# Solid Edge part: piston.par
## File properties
Author: Robert a Rhodes jr
Template: normal.par
Last saved by: CADCIM
Revision: 11
Application: Solid Edge
Accuracy: 0.99
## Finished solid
Body 1: solid body, 42 faces, 58 edges, 16 vertices.
  Faces by surface: cylinder 21, plane 20, torus 1
  Edges by curve: circle 40, intersection 10, line 8
Bounding box of the edges (mm; curved faces can reach further): 93.000 x 93.000 x 66.000, from (-46.5, -46.5, -46) to (46.5, 46.5, 20).
Cylindrical faces by radius (mm): R10 x2, R15 x2, R19 x2, R37 x2, R38.5 x2, R42.5 x5, R46.5 x6
Toroidal faces (ring radius, tube radius in mm): R-5.5431 r189 x1
Planar faces by outward normal: +y 2, +z 7, -y 2, -z 9
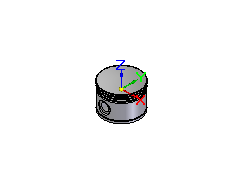
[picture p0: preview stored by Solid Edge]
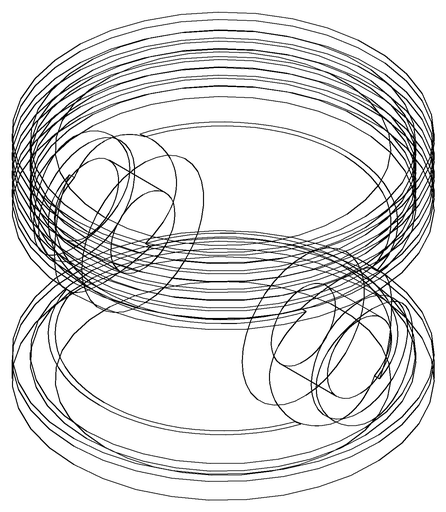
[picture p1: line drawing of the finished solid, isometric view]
